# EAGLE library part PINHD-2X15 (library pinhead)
PIN HEADER
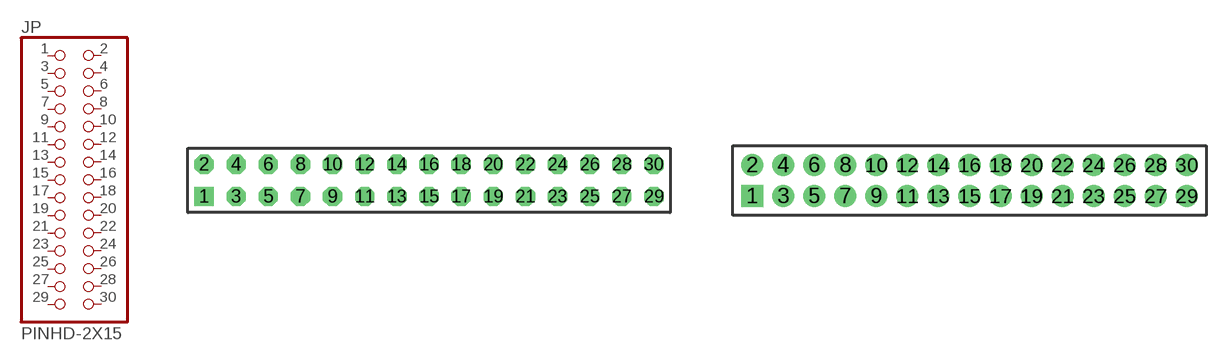
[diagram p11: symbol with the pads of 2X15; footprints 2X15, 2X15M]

Designator prefix JP

## PINHD-2X15  [2X15]
1  1  pas
2  2  pas
3  3  pas
4  4  pas
5  5  pas
6  6  pas
7  7  pas
8  8  pas
9  9  pas
10  10  pas
11  11  pas
12  12  pas
13  13  pas
14  14  pas
15  15  pas
16  16  pas
17  17  pas
18  18  pas
19  19  pas
20  20  pas
21  21  pas
22  22  pas
23  23  pas
24  24  pas
25  25  pas
26  26  pas
27  27  pas
28  28  pas
29  29  pas
30  30  pas

## PINHD-2X15M  [2X15M]
Pads as for 2X15

## Footprint 2X15 (pad centres in mm)
PIN HEADER - 0.1"
drill 1.016 square: 1 -17.78,-1.27
drill 1.016 octagon: 2 -17.78,1.27; 3 -15.24,-1.27; 4 -15.24,1.27; 5 -12.7,-1.27; 6 -12.7,1.27; 7 -10.16,-1.27; 8 -10.16,1.27; 9 -7.62,-1.27; 10 -7.62,1.27; 11 -5.08,-1.27; 12 -5.08,1.27; 13 -2.54,-1.27; 14 -2.54,1.27; 15 0,-1.27; 16 0,1.27; 17 2.54,-1.27; 18 2.54,1.27; 19 5.08,-1.27; 20 5.08,1.27; 21 7.62,-1.27; 22 7.62,1.27; 23 10.16,-1.27; 24 10.16,1.27; 25 12.7,-1.27; 26 12.7,1.27; 27 15.24,-1.27; 28 15.24,1.27; 29 17.78,-1.27; 30 17.78,1.27

## Footprint 2X15M (pad centres in mm)
PIN HEADER - 2MM"
drill 0.914 square: 1 -14,-1
drill 0.914 round: 2 -14,1; 3 -12,-1; 4 -12,1; 5 -10,-1; 6 -10,1; 7 -8,-1; 8 -8,1; 9 -6,-1; 10 -6,1; 11 -4,-1; 12 -4,1; 13 -2,-1; 14 -2,1; 15 0,-1; 16 0,1; 17 2,-1; 18 2,1; 19 4,-1; 20 4,1; 21 6,-1; 22 6,1; 23 8,-1; 24 8,1; 25 10,-1; 26 10,1; 27 12,-1; 28 12,1; 29 14,-1; 30 14,1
